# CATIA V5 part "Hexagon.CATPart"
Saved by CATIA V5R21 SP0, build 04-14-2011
Part number: Hezagon
Bounding box of the stored display mesh (mm): x -50 to 50, y -43.301 to 43.301, z -50 to 50
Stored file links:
  D:\CATIA V5R21 E-RESOURCES\CATIA-V5R21\catia-v5r21-prt\c16-catia-v5r20-prt\Cylindrical Joint(Fig16-18)\CAT_V5R21_Hexagon.CATPart
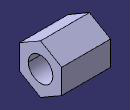
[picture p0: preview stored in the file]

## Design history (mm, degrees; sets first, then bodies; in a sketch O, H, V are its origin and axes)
Body1 (main body)
  Sketch1 on yz-plane, origin (0, 0, 0), H (0, 1, 0), V (0, 0, 1)
    point P1 (43.3013, -25)
    point P2 (43.3013, 25)
    point P3 (0, 50)
    point P4 (-43.3013, 25)
    point P5 (-43.3013, -25)
    point P6 (0, -50)
    point P7 (43.3013, 0)
    line L1 (43.3013, -25) -> (43.3013, 25)
    line L2 (43.3013, 25) -> (0, 50)
    line L3 (0, 50) -> (-43.3013, 25)
    line L4 (-43.3013, 25) -> (-43.3013, -25)
    line L5 (-43.3013, -25) -> (0, -50)
    line L6 (0, -50) -> (43.3013, -25)
    construction line L7 (0, 0) -> (43.3013, 0)
    construction circle A1 centre (0, 0) radius 50
    construction arc A2 centre (-43.3013, -25) radius 50 from (-43.3013, 25) to (0, -50) cw
    construction arc A3 centre (43.3013, 25) radius 50 from (0, 50) to (43.3013, -25) ccw
    circle A4 centre (0, 0) radius 25
    radius A4 = 25
    length L1 = 50
    horizontal: L7 H
    coincidence: A1 P1, A1 P2, A1 P3, A1 P4, A1 P5, A1 P6, A2 O, A3 O
    midpoint: P7 L1
    parallelism: L1 L4
  Pad1: profile Sketch1, direction (1, 0, 0), length 50, mirrored extent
